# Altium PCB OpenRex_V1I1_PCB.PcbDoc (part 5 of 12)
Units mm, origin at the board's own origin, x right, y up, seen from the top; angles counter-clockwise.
Board outline 70 x 95 mm, 10 copper layers (L1, L2, L3, L4 (PWR), L5 (PWR), L6 (PWR), L7 (PWR), L8, L9, L10), stack 1.632 mm thick; 1080 components, 708 nets, 3831 pads, 2373 vias.
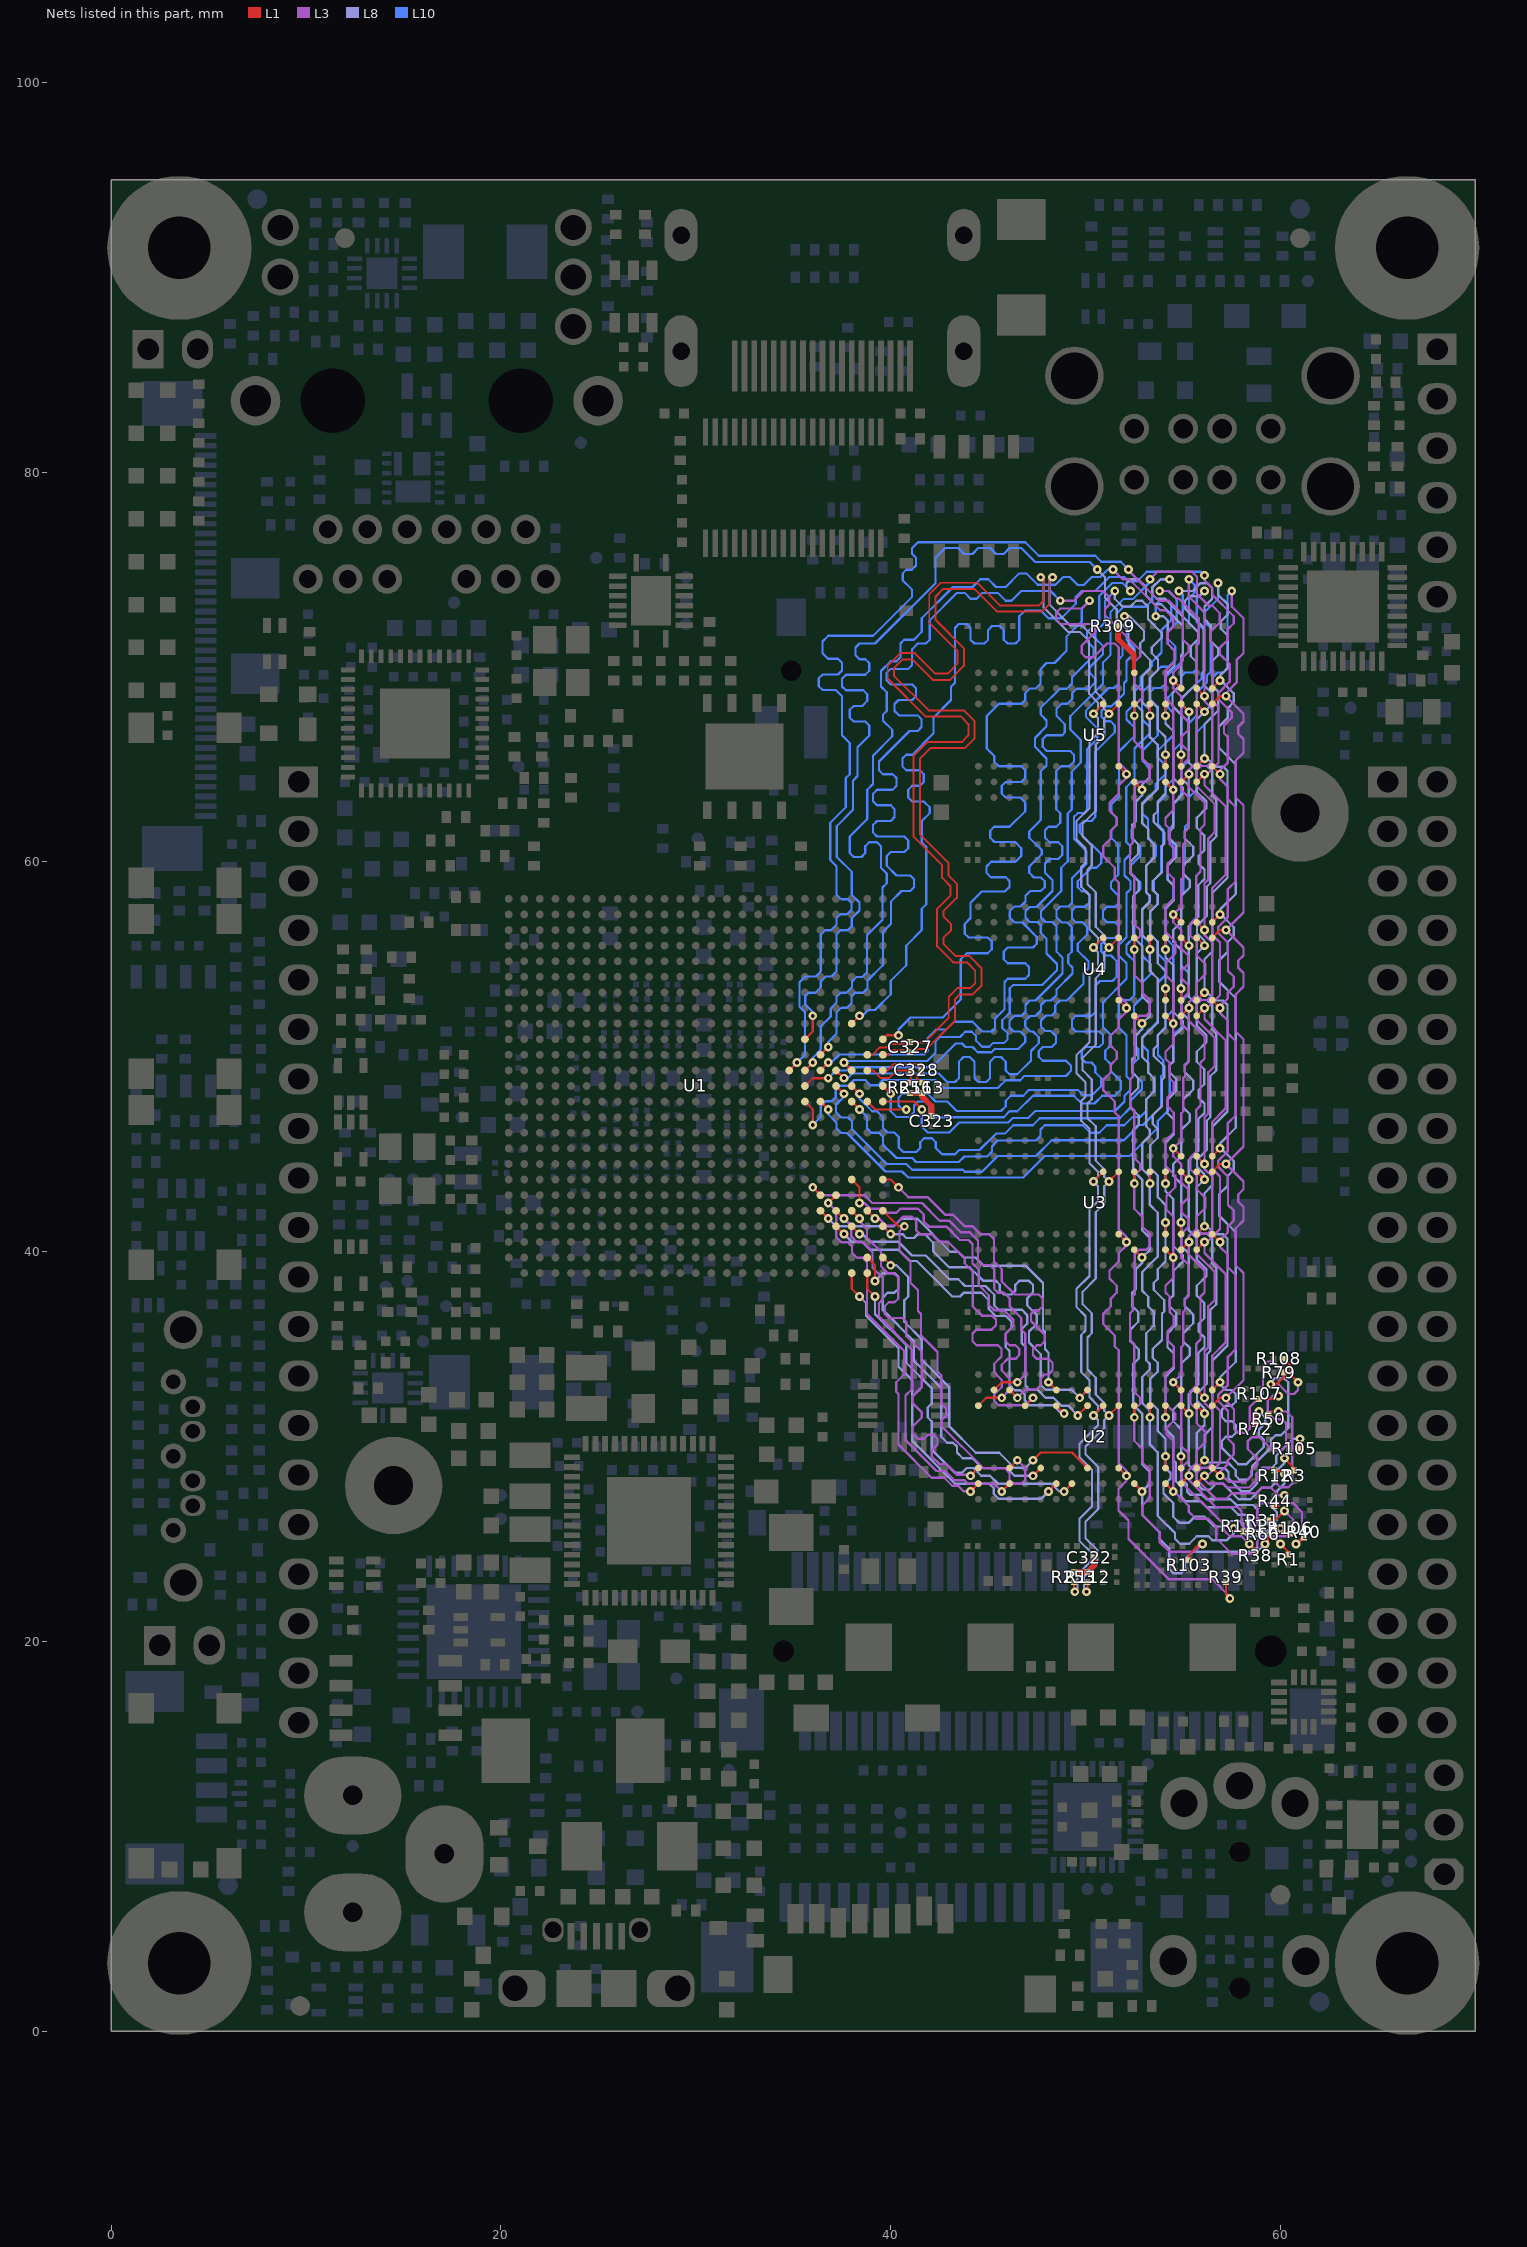
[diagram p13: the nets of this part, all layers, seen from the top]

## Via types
v1: diameter 0.45, hole 0.2, L1 to L10, tented both sides, 2369 vias
v2: diameter 1, hole 0.5, L1 to L10, tented top, 4 vias

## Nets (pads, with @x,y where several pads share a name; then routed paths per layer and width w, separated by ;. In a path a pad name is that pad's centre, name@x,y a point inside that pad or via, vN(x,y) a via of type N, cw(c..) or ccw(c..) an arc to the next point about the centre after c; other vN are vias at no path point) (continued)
DRAM3_ZQ1: R309.2 U5.L9 | length 2.7
  L1 w0.19: 52.48,70.44 52.48,69.72 U5.L9@52.5,69.7
  L1 w0.3: R309.2@51.665,72.1 51.665,71.435 52.46,70.64 52.46,70.46
DRAM_A0: R1.1 U1.AC14 U2.N3 U3.N3 U4.N3 U5.N3 | length 109.6
  L1 w0.114: v1(37.6,49.7) U1.AC14@38,49.3 ; U2.N3@54.1,28.9 v1(54.1,29.5) ; U3.N3@54.1,40.9 v1(54.1,41.5) ; U4.N3@54.1,52.9 v1(54.1,53.5) ; U5.N3@54.1,64.9 v1(54.1,65.5) ; v1(60,25) 60.4,24.6 R1.1@60.4,24.465
  L8 w0.12: v1(51.5,73.9) 51.5,73.5 51.9,73.1 52.3,73.1 52.6,73.4 52.9,73.4 53.2,73.1 53.2,72.456 53.9,71.756 53.9,71.5 53.4,71 53.4,70.7 53.715,70.385 53.715,69.859 53.3,69.444 53.3,68.3 53.7,67.9 53.7,66.8 54.1,66.4 v1(54.1,65.5) 54.1,63.5 53.7,63.1 53.7,62.6 53.5,62.4 53.5,62.044 54.035,61.509 54.035,60.935 53.92,60.82 53.92,59.476 53.45,59.006 53.45,58.55 53.7,58.3 53.7,57.844 53.315,57.459 53.315,56.29 53.7,55.905 53.7,54.8 54.1,54.4 v1(54.1,53.5) 54.1,51.5 53.7,51.1 53.7,50.6 53.5,50.4 53.5,50.044 54.035,49.509 54.035,48.935 53.92,48.82 53.92,47.476 53.45,47.006 53.45,46.55 53.7,46.3 53.7,45.844 53.315,45.459 53.315,44.29 53.7,43.905 53.7,42.8 54.1,42.4 v1(54.1,41.5) 54.1,39.5 53.7,39.1 53.7,38.6 53.5,38.4 53.5,38.044 54.035,37.509 54.035,36.935 53.92,36.82 53.92,35.476 53.45,35.006 53.45,34.55 53.7,34.3 53.7,33.844 53.315,33.459 53.315,32.29 53.7,31.905 53.7,30.8 54.1,30.4 v1(54.1,29.5) 54.1,28.9 54.355,28.645 54.355,28.355 54,28 54,27.6 54.5,27.1 54.5,26.4 54.8,26.1 55.3,26.1 55.615,26.415 56.085,26.415 56.6,25.9 57.144,25.9 57.429,26.185 57.915,26.185 58.1,26 58.1,25.6 58.315,25.385 59.615,25.385 v1(60,25)
  L10 w0.114: v1(37.6,49.7) 37.689,49.789 41.889,49.789 42.3,50.2 42.3,50.8 42.515,51.015 43.559,51.015 43.829,51.285 44.159,51.285 44.385,51.059 44.385,50.815 44.685,50.515 45.059,50.515 45.244,50.7 45.8,50.7 46,50.9 46,51.2 45.728,51.472 45.728,51.868 46.115,52.255 46.115,53.515 46.285,53.685 47.779,53.685 48.535,54.441 48.535,54.759 48,55.294 48,56.055 47.7,56.355 47.7,56.751 47.536,56.915 47.141,56.915 46.915,57.141 46.915,57.459 47.141,57.685 47.485,57.685 48.3,58.5 48.3,59.056 47.915,59.441 47.915,59.915 48.15,60.15 48.6,60.15 48.8,60.35 48.8,60.8 48.6,61 48.156,61 47.915,61.241 47.915,61.615 48.1,61.8 48.5,61.8 48.7,62 48.7,62.5 48.5,62.7 48.5,64.644 48.756,64.9 49.16,64.9 49.4,65.14 49.4,65.5 49.215,65.685 48.015,65.685 47.8,65.9 47.8,66.3 48,66.5 48.8,66.5 48.935,66.635 48.935,67.065 48.515,67.485 48.515,67.859 48.77,68.115 49.059,68.115 49.315,68.371 49.315,68.659 49.541,68.885 50.185,68.885 50.5,69.2 50.5,69.4 50.2,69.7 50.2,69.969 50.9,70.669 50.9,71.056 50.5,71.456 50.5,71.8 51,72.3 51,73.4 v1(51.5,73.9)
DRAM_A1: R3.1 U1.AB14 U2.P7 U3.P7 U4.P7 U5.P7 | length 109.5
  L1 w0.114: U1.AB14@37.2,49.3 v1(37.6,48.9) ; U2.P7@54.9,32.1 v1(55.3,31.7) ; U3.P7@54.9,44.1 v1(55.3,43.7) ; U4.P7@54.9,56.1 v1(55.3,55.7) ; U5.P7@54.9,68.1 v1(55.3,67.7) ; v1(60.2,29.4) 60.7,28.9 R3.1@60.7,28.765
  L8 w0.12: v1(54.3,74.5) 53.844,74.5 53.415,74.071 53.415,73.741 53.656,73.5 54.08,73.5 55.785,71.795 55.785,71.441 55.4,71.056 55.4,70.544 55.7,70.244 55.7,69.156 54.944,68.4 54.944,68.056 v1(55.3,67.7) 55.3,65.082 55.7,64.682 55.7,63.6 56.2,63.1 56.2,62.756 55.7,62.256 55.7,61.744 56.085,61.359 56.085,60.585 55.81,60.31 55.81,59.89 56.1,59.6 56.1,59.115 55.785,58.8 55.785,57.181 55.3,56.696 v1(55.3,55.7) 55.3,53.082 55.7,52.682 55.7,51.6 56.2,51.1 56.2,50.756 55.7,50.256 55.7,49.744 56.085,49.359 56.085,48.585 55.81,48.31 55.81,47.89 56.1,47.6 56.1,47.115 55.785,46.8 55.785,45.181 55.3,44.696 v1(55.3,43.7) 55.3,41.082 55.7,40.682 55.7,39.6 56.2,39.1 56.2,38.756 55.7,38.256 55.7,37.744 56.085,37.359 56.085,36.585 55.81,36.31 55.81,35.89 56.1,35.6 56.1,35.115 55.785,34.8 55.785,33.181 55.3,32.696 v1(55.3,31.7) 55.3,29.044 55.7,28.644 55.7,28.1 56,27.8 56.4,27.8 56.7,28.1 57.044,28.1 57.844,27.3 58.456,27.3 59.056,27.9 59.5,27.9 59.815,28.215 59.815,28.775 60.2,29.16 v1(60.2,29.4)
  L10 w0.114: v1(37.6,48.9) 37.796,48.9 38.033,49.137 42.463,49.137 42.9,48.7 43.3,48.7 43.5,48.9 43.5,49.744 43.741,49.985 44.059,49.985 44.3,49.744 44.3,48.9 44.5,48.7 44.9,48.7 45.1,48.9 45.1,49.744 45.341,49.985 45.659,49.985 45.9,49.744 45.9,49.3 46.1,49.1 46.5,49.1 47.2,49.8 47.2,50.3 47.6,50.7 47.6,51 47.3,51.3 47.156,51.3 46.9,51.556 46.9,51.844 47.146,52.091 47.435,52.091 47.715,52.371 47.715,52.659 47.941,52.885 48.229,52.885 48.515,53.171 48.515,53.459 49.33,54.274 49.33,54.585 49.115,54.8 49.115,55.215 49.285,55.385 49.285,56.659 49.059,56.885 48.771,56.885 48.515,57.141 48.515,57.515 48.715,57.715 49.115,57.715 49.3,57.9 49.3,59.156 50.05,59.906 50.05,60.55 49.4,61.2 49.4,62.3 49.6,62.5 49.9,62.5 50.085,62.685 50.085,65.785 50.6,66.3 50.6,66.856 50.015,67.441 50.015,67.759 51.171,68.915 51.459,68.915 51.685,69.141 51.685,70.385 51.9,70.6 51.9,71.2 51.615,71.485 51.615,72.759 51.941,73.085 53.085,73.085 53.415,73.415 53.415,74.059 53.856,74.5 v1(54.3,74.5)
DRAM_A2: R12.1 U1.AA14 U2.P3 U3.P3 U4.P3 U5.P3 | length 109.6
  L1 w0.114: U1.AA14@36.4,49.3 v1(36.8,49.7) ; U2.P3@54.9,28.9 v1(54.9,29.5) ; U3.P3@54.9,40.9 v1(54.9,41.5) ; U4.P3@54.9,52.9 v1(54.9,53.5) ; U5.P3@54.9,64.9 v1(54.9,65.5) ; R12.1@59.7,28.765 60.035,28.765 v1(60.2,28.6)
  L8 w0.12: v1(52.3,73.9) 52.1,74.1 52.1,74.3 52.3,74.5 52.7,74.5 53.1,74.1 53.1,73.66 53.54,73.22 53.88,73.22 55,72.1 55,70.7 54.9,70.6 54.9,69.1 54.456,68.656 54.456,68 54.9,67.556 v1(54.9,65.5) 54.9,64.3 55.3,63.9 55.3,61.8 55.085,61.585 55.085,61.215 55.525,60.775 55.525,60.325 55,59.8 55,59.4 55.35,59.05 55.35,58.694 54.9,58.244 54.9,56.9 54.5,56.5 54.5,55.9 54.9,55.5 v1(54.9,53.5) 54.9,52.3 55.3,51.9 55.3,49.8 55.085,49.585 55.085,49.215 55.525,48.775 55.525,48.325 55,47.8 55,47.4 55.35,47.05 55.35,46.694 54.9,46.244 54.9,44.9 54.5,44.5 54.5,43.9 54.9,43.5 v1(54.9,41.5) 54.9,40.3 55.3,39.9 55.3,37.8 55.085,37.585 55.085,37.215 55.525,36.775 55.525,36.325 55,35.8 55,35.4 55.35,35.05 55.35,34.694 54.9,34.244 54.9,32.3 54.5,31.9 54.5,31.3 54.9,30.9 v1(54.9,29.5) 54.915,29.485 54.915,28.341 55.2,28.055 55.2,27.7 55.38,27.52 55.98,27.52 56.2,27.3 57.436,27.3 57.736,27 58.6,27 58.8,26.8 58.8,26.2 59,26 59.6,26 59.815,26.215 59.815,26.629 59.5,26.944 59.5,27.256 59.8,27.556 59.8,27.7 60.2,28.1 v1(60.2,28.6)
  L10 w0.114: v1(36.8,49.7) 36.955,49.7 37.37,50.115 41.715,50.115 41.9,50.3 41.9,50.967 42.325,51.392 42.847,51.392 43.256,51.8 44.2,51.8 44.7,51.3 45.2,51.3 45.348,51.448 45.348,51.948 45.835,52.435 45.835,53.835 46,54 46.9,54 47.1,54.2 47.1,54.6 46.9,54.8 46,54.8 45.8,55 45.8,55.4 46,55.6 47.3,55.6 47.5,55.8 47.5,56.144 46.759,56.885 46.37,56.885 46.115,57.141 46.115,57.459 46.371,57.715 46.659,57.715 46.915,57.971 46.915,58.259 47.156,58.5 47.7,58.5 47.9,58.7 47.9,59 47.7,59.2 47.356,59.2 47.115,59.441 47.115,59.759 47.75,60.394 47.75,60.606 47.115,61.241 47.115,61.559 47.7,62.144 47.7,64.644 48,64.944 48,65.3 47.4,65.9 47.4,66.356 48,66.956 48,67.256 47.7,67.556 47.7,67.9 48.685,68.885 49.029,68.885 49.3,69.156 49.3,69.465 50.4,70.565 50.4,71 50.075,71.325 50.075,71.785 50.7,72.41 50.7,73.644 51.356,74.3 51.9,74.3 v1(52.3,73.9)
DRAM_A3: R31.1 U1.Y14 U2.N2 U3.N2 U4.N2 U5.N2 | length 109.5
  L1 w0.114: U1.Y14@35.6,49.3 v1(36,49.7) ; U2.N2@54.1,28.1 v1(54.5,27.7) ; U3.N2@54.1,40.1 v1(54.5,39.7) ; U4.N2@54.1,52.1 v1(54.5,51.7) ; U5.N2@54.1,64.1 v1(54.5,63.7) ; R31.1@59.365,26.2 59.7,26.2 v1(60.2,26.7)
  L3 w0.12: v1(51.4,75) 51.9,74.5 52.244,74.5 53.834,72.91 54.09,72.91 54.5,72.5 54.5,72.044 54.215,71.759 54.215,71.185 54.58,70.82 54.58,70.28 54.115,69.815 54.115,68.385 54.5,68 v1(54.5,63.7) 54.5,62.656 54.1,62.256 54.1,61.9 54.315,61.685 54.315,60.9 54.525,60.69 54.525,60.238 54.215,59.928 54.215,59.441 54.525,59.131 54.525,58.125 54.1,57.7 54.1,56.4 54.6,55.9 54.6,55.3 54.15,54.85 54.15,54.15 54.5,53.8 v1(54.5,51.7) 54.5,50.656 54.1,50.256 54.1,49.9 54.315,49.685 54.315,48.9 54.525,48.69 54.525,48.238 54.215,47.928 54.215,47.441 54.525,47.131 54.525,46.125 54.1,45.7 54.1,44.4 54.6,43.9 54.6,43.3 54.15,42.85 54.15,42.15 54.5,41.8 v1(54.5,39.7) 54.5,38.656 54.1,38.256 54.1,37.9 54.315,37.685 54.315,36.9 54.525,36.69 54.525,36.238 54.215,35.928 54.215,35.441 54.525,35.131 54.525,34.125 54.1,33.7 54.1,32.2 54.6,31.7 54.6,31.4 54.15,30.95 54.15,30.65 54.5,30.3 v1(54.5,27.7) 54.544,27.7 55.285,26.959 55.285,26.671 55.656,26.3 56.3,26.3 56.7,25.9 56.7,25.3 57.5,24.5 58.556,24.5 58.8,24.744 58.8,25.144 59.056,25.4 60.45,25.4 60.65,25.6 60.65,26.25 v1(60.2,26.7)
  L10 w0.114: v1(36,49.7) 36,49.956 36.415,50.371 36.415,51.56 36.925,52.07 36.925,52.481 37.215,52.771 37.215,53.059 37.441,53.285 37.729,53.285 38.015,53.571 38.015,53.859 38.241,54.085 38.529,54.085 38.785,54.341 38.785,56.229 39.585,57.029 39.585,58.685 39.8,58.9 39.8,59.404 39.5,59.704 39.5,60.8 39.3,61 38.9,61 38.7,60.8 38.7,60.45 38.5,60.25 38.1,60.25 37.9,60.45 37.9,61.3 38.8,62.2 38.8,63.7 39.09,63.99 39.09,65.446 40.085,66.441 40.085,66.771 39.6,67.256 39.6,67.544 39.8,67.744 39.8,68.7 39.5,69 39.5,69.796 40,70.296 40.296,70.296 40.5,70.5 40.5,71.2 40.7,71.4 41.2,71.4 41.6,71.8 41.6,72.5 43.2,74.1 44.2,74.1 44.6,74.5 45.004,74.5 45.404,74.1 45.9,74.1 46.6,74.8 46.956,74.8 47.541,74.215 48.459,74.215 48.859,74.615 49.185,74.615 49.6,74.2 49.9,74.2 50.315,74.615 50.759,74.615 51.144,75 v1(51.4,75)
DRAM_A4: R38.1 U1.W14 U2.P8 U3.P8 U4.P8 U5.P8 | length 109.4
  L1 w0.114: U1.W14@34.8,49.3 v1(35.2,49.7) ; v1(54.5,33.3) U2.P8@54.9,32.9 ; v1(54.5,45.3) U3.P8@54.9,44.9 ; v1(54.5,57.3) U4.P8@54.9,56.9 ; v1@54.5,69.3 U5.P8@54.9,68.9 ; v1(58.4,25) 58.7,24.7 R38.1@58.7,24.665
  L3 w0.12: v1(52.2,75) 52.2,74.955 53.755,73.4 54.28,73.4 55,72.68 55,71.4 55.3,71.1 55.3,70.8 54.9,70.4 54.9,70.1 54.5,69.7 v1(54.5,69.3) 54.5,68.9 54.9,68.5 54.9,67.556 55.275,67.181 55.275,66.775 54.9,66.4 54.9,66.044 55.3,65.644 55.3,65.3 54.9,64.9 54.9,63.7 55.3,63.3 55.3,61.744 55.1,61.544 55.1,61 55.015,60.915 55.015,59.2 54.915,59.1 54.915,57.715 v1(54.5,57.3) 54.5,56.9 54.9,56.5 54.9,55.556 55.275,55.181 55.275,54.775 54.9,54.4 54.9,54.044 55.3,53.644 55.3,53.3 54.9,52.9 54.9,51.7 55.3,51.3 55.3,49.744 55.1,49.544 55.1,49 55.015,48.915 55.015,47.2 54.915,47.1 54.915,45.715 v1(54.5,45.3) 54.5,44.9 54.9,44.5 54.9,43.556 55.275,43.181 55.275,42.775 54.9,42.4 54.9,42.044 55.3,41.644 55.3,41.3 54.9,40.9 54.9,39.7 55.3,39.3 55.3,37.744 55.1,37.544 55.1,37 55.015,36.915 55.015,35.2 54.915,35.1 54.915,33.715 v1(54.5,33.3) 54.9,32.9 54.9,30.044 55.3,29.644 55.3,29.3 54.9,28.9 54.9,28.2 57.1,26 57.1,25.7 57.4,25.4 58,25.4 v1(58.4,25)
  L10 w0.114: v1(35.2,49.7) 35.6,50.1 35.6,52.29 35.325,52.565 35.325,53.825 35.615,54.115 36.159,54.115 36.415,54.371 36.415,56.259 36.641,56.485 36.929,56.485 37.215,56.771 37.215,57.1 37.43,57.315 37.759,57.315 37.985,57.541 37.985,57.9 37.8,58.085 37.471,58.085 37.215,58.341 37.215,59.785 36.9,60.1 36.9,62 37.7,62.8 37.7,64.3 37.9,64.5 37.9,66.1 37.5,66.5 37.5,68.5 37.185,68.815 36.515,68.815 36.315,69.015 36.315,69.415 36.515,69.615 37.3,69.615 37.5,69.815 37.5,70.215 37.3,70.415 36.785,70.415 36.5,70.7 36.5,71.3 36.8,71.6 39.1,71.6 41.1,73.6 41.1,73.956 40.615,74.441 40.615,74.8 40.8,74.985 41.085,74.985 41.3,75.2 41.3,75.6 41.1,75.8 41.1,76.1 41.4,76.4 46.9,76.4 47.6,75.7 50.5,75.7 50.8,75.4 51.8,75.4 v1(52.2,75)
DRAM_A5: R40.1 U1.AE13 U2.P2 U3.P2 U4.P2 U5.P2 | length 109.4
  L1 w0.114: U1.AE13@39.6,48.5 v1(40,48.1) ; U2.P2@54.9,28.1 v1(55.3,28.5) ; U3.P2@54.9,40.1 v1(55.3,40.5) ; U4.P2@54.9,52.1 v1(55.3,52.5) ; U5.P2@54.9,64.1 v1(55.3,64.5) ; v1(60.8,25) 60.865,25 R40.1@61.2,25.335
  L3 w0.12: v1(53.8,73.9) 54.256,73.9 54.641,73.515 54.785,73.515 55.8,72.5 55.8,71.2 55.7,71.1 55.7,65.118 55.3,64.718 v1(55.3,64.5) 55.3,63.829 56.1,63.029 56.1,61.9 55.9,61.7 55.9,59.5 55.685,59.285 55.685,57.141 55.375,56.831 55.375,56.225 55.7,55.9 55.7,55.2 56.15,54.75 56.15,54.25 55.7,53.8 55.7,53.2 55.3,52.8 v1(55.3,52.5) 55.3,51.829 56.1,51.029 56.1,49.9 55.9,49.7 55.9,47.5 55.685,47.285 55.685,45.141 55.375,44.831 55.375,44.225 55.7,43.9 55.7,43.2 56.15,42.75 56.15,42.25 55.7,41.8 55.7,41.2 55.3,40.8 v1(55.3,40.5) 55.3,39.829 56.1,39.029 56.1,37.9 55.9,37.7 55.9,35.5 55.685,35.285 55.685,33.141 55.375,32.831 55.375,32.225 55.7,31.9 55.7,31.2 56.15,30.75 56.15,30.25 55.7,29.8 55.7,29.2 55.3,28.8 v1(55.3,28.5) 55.3,28.282 56.682,26.9 57.8,26.9 58,26.7 58,26 58.2,25.8 58.6,25.8 58.8,26 58.8,26.9 59,27.1 60.635,27.1 61.1,26.635 61.1,25.3 v1(60.8,25)
  L10 w0.114: v1(40,48.1) 40,47.2 40.285,46.915 40.959,46.915 41.2,47.156 41.2,47.5 41.4,47.7 41.8,47.7 42,47.5 42,47.1 42.2,46.9 45.8,46.9 46.1,47.2 46.5,47.2 47.3,48 49.4,48 49.8,47.6 50.456,47.6 50.856,48 51.5,48 51.8,48.3 51.8,48.756 51.3,49.256 51.3,49.6 51.006,49.894 51.006,50.306 51.3,50.6 51.3,51.1 50.9,51.5 50.9,52.8 52.1,54 52.1,54.8 51.7,55.2 51.7,55.735 52.1,56.135 52.1,58.4 52.3,58.6 52.3,59 52,59.3 52,60.1 52.3,60.4 52.3,60.8 52.085,61.015 52.085,63.825 52.515,64.255 52.515,65.815 53.3,66.6 53.3,66.9 52.9,67.3 52.9,68.7 53.315,69.115 53.315,69.459 53.871,70.015 54.259,70.015 54.6,70.356 54.6,71.056 54.215,71.441 54.215,71.815 54.68,72.28 54.68,73.476 54.256,73.9 v1(53.8,73.9)
DRAM_A6: R44.1 U1.AC13 U2.R8 U3.R8 U4.R8 U5.R8 | length 109.4
  L1 w0.114: U1.AC13@38,48.5 v1(38.4,48.1) ; U2.R8@55.7,32.9 v1(56.1,32.5) ; U3.R8@55.7,44.9 v1(56.1,44.5) ; U4.R8@55.7,56.9 v1(56.1,56.5) ; U5.R8@55.7,68.9 v1(56.1,68.5) ; R44.1@59.7,26.935 59.869,26.935 60.2,27.266 v1(60.2,27.5)
  L3 w0.12: v1(55.3,74.5) 55.3,73.6 56.1,72.8 v1(56.1,68.5) 56.1,68.244 56.5,67.844 56.5,65.156 56.259,64.915 55.915,64.915 55.7,64.7 55.7,63.882 56.625,62.957 56.625,61.525 56.3,61.2 56.3,59.1 56.1,58.9 v1(56.1,56.5) 56.1,56.244 56.5,55.844 56.5,53.156 56.259,52.915 55.915,52.915 55.7,52.7 55.7,51.882 56.625,50.957 56.625,49.525 56.3,49.2 56.3,47.1 56.1,46.9 v1(56.1,44.5) 56.1,44.244 56.5,43.844 56.5,41.156 56.259,40.915 55.915,40.915 55.7,40.7 55.7,39.882 56.625,38.957 56.625,37.525 56.3,37.2 56.3,35.1 56.1,34.9 v1(56.1,32.5) 56.1,32.244 56.5,31.844 56.5,29.156 56.259,28.915 55.971,28.915 55.7,28.644 55.7,28.304 56.689,27.315 57.215,27.315 57.5,27.6 58.756,27.6 59.041,27.885 59.515,27.885 59.9,27.5 v1(60.2,27.5)
  L10 w0.114: v1(38.4,48.1) 38.4,47.85 39.05,47.2 39.3,47.2 39.6,46.9 39.6,46.356 39.841,46.115 40.185,46.115 40.415,45.885 40.415,45.341 40.641,45.115 41.315,45.115 41.515,45.315 41.515,45.615 41.715,45.815 42.115,45.815 42.315,45.615 42.315,45.315 42.63,45 43.3,45 43.515,45.215 44.559,45.215 45.4,46.056 45.856,46.056 46.285,46.485 47.285,46.485 47.65,46.85 51.75,46.85 52.3,47.4 52.3,47.744 52.9,48.344 52.9,48.7 52.415,49.185 52.415,49.615 52.7,49.9 52.7,50.4 52.485,50.615 52.485,52.629 52.9,53.044 52.9,53.8 53.35,54.25 53.35,54.75 52.9,55.2 52.9,57.556 53.285,57.941 53.285,58.259 53.1,58.444 53.1,59.8 53.6,60.3 53.6,60.856 53.2,61.256 53.2,62.2 52.9,62.5 52.9,63 53.6,63.7 53.6,64 54.1,64.5 54.1,64.956 53.7,65.356 53.7,65.7 54.485,66.485 54.485,67.659 54.244,67.9 54.244,68.444 54.9,69.1 54.9,69.5 55.115,69.715 55.515,69.715 55.685,69.885 55.685,71.285 55.8,71.4 55.8,71.744 55.3,72.244 55.3,73.52 55.6,73.82 55.6,74.2 v1(55.3,74.5)
DRAM_A7: R50.1 U1.Y13 U2.R2 U3.R2 U4.R2 U5.R2 | length 109.5
  L1 w0.114: U1.Y13@35.6,48.5 36,48.9 v1(36.8,48.9) ; U2.R2@55.7,28.1 v1(56.1,28.5) ; U3.R2@55.7,40.1 v1(56.1,40.5) ; U4.R2@55.7,52.1 v1(56.1,52.5) ; U5.R2@55.7,64.1 v1(56.1,64.5) ; R50.1@59.4,31.665 59.535,31.8 v1(59.9,31.8)
  L3 w0.12: v1(53.3,74.5) 53.685,74.885 55.459,74.885 55.715,74.629 55.715,73.741 56.1,73.356 56.318,73.137 56.507,73.137 56.885,72.759 56.885,72.285 56.415,71.815 56.415,71.3 56.5,71.215 56.5,68.26 56.82,67.94 56.82,65.08 56.24,64.5 v1(56.1,64.5) 56.1,63.934 57.185,62.849 57.185,59.341 56.5,58.656 56.5,56.26 56.9,55.86 56.9,53.16 56.24,52.5 v1(56.1,52.5) 56.1,51.934 57.185,50.849 57.185,47.341 56.5,46.656 56.5,44.26 56.9,43.86 56.9,41.16 56.24,40.5 v1(56.1,40.5) 56.1,39.934 57.185,38.849 57.185,35.341 56.5,34.656 56.5,32.24 56.9,31.84 56.9,29.16 56.24,28.5 v1(56.1,28.5) 56.1,28.3 56.315,28.085 57.059,28.085 57.244,27.9 58.4,27.9 58.765,28.265 58.765,28.61 59.041,28.885 59.515,28.885 59.74,28.66 59.74,28.16 59.985,27.915 60.415,27.915 60.6,28.1 60.6,31.5 60.3,31.8 v1(59.9,31.8)
  L10 w0.114: v1(36.8,48.9) 37.2,49.3 37.744,49.3 37.907,49.463 42.119,49.463 43.341,50.685 43.659,50.685 43.844,50.5 44.2,50.5 44.465,50.235 45.175,50.235 45.34,50.4 46.544,50.4 46.9,50.756 46.9,51.044 46.644,51.3 46.3,51.3 46.1,51.5 46.1,51.844 46.356,52.1 46.715,52.1 46.915,52.3 46.915,52.659 47.141,52.885 47.429,52.885 48.815,54.271 48.815,55.085 48.515,55.385 48.515,56.685 48.285,56.915 47.941,56.915 47.715,57.141 47.715,57.459 48.756,58.5 48.756,59.7 49.08,60.024 49.08,62.484 49.285,62.689 49.285,64.629 49.75,65.094 49.75,66.25 49.215,66.785 49.215,67.471 50.9,69.156 50.9,70.244 51.285,70.629 51.285,72.825 51.94,73.48 52.424,73.48 53.3,74.356 v1(53.3,74.5)
DRAM_A8: R72.1 U1.AB13 U2.T8 U3.T8 U4.T8 U5.T8 | length 109.5
  L1 w0.114: U1.AB13@37.2,48.5 v1(37.6,48.1) ; U2.T8@56.5,32.9 v1(56.9,33.3) ; U3.T8@56.5,44.9 v1(56.9,45.3) ; U4.T8@56.5,56.9 v1(56.9,57.3) ; U5.T8@56.5,68.9 v1@56.9,69.3 ; R72.1@58.7,31.165 58.7,31.6 v1(58.9,31.8)
  L8 w0.12: v1(56.8,74.3) 56.8,73.7 57.3,73.2 57.3,72.7 56.932,72.332 56.932,71.968 57.3,71.6 57.3,69.956 56.9,69.556 v1(56.9,69.3) 56.944,69.3 57.6,68.644 57.6,68.2 57.3,67.9 57.3,67.4 56.845,66.945 56.845,65.855 57.7,65 57.7,58.356 56.9,57.556 v1(56.9,57.3) 56.944,57.3 57.6,56.644 57.6,56.2 57.3,55.9 57.3,55.4 56.845,54.945 56.845,53.855 57.7,53 57.7,46.356 56.9,45.556 v1(56.9,45.3) 56.944,45.3 57.6,44.644 57.6,44.2 57.3,43.9 57.3,43.4 56.845,42.945 56.845,41.855 57.7,41 57.7,34.356 56.9,33.556 v1(56.9,33.3) 56.9,33.2 57.2,32.9 57.5,32.9 57.7,32.7 57.7,32.3 57.5,32.1 57.2,32.1 57,31.9 57,31.5 57.2,31.3 57.5,31.3 57.7,31.1 57.7,30.7 57.5,30.5 57.2,30.5 57,30.3 57,29.934 57.834,29.1 58.26,29.1 59.15,29.99 59.15,30.35 58.9,30.6 58.9,30.88 59.22,31.2 59.22,31.48 v1(58.9,31.8)
  L10 w0.114: v1(37.6,48.1) 37.6,47.945 37.2,47.545 37.2,47.156 37.471,46.885 37.815,46.885 38.015,46.685 38.015,46.285 39.8,44.5 40.8,44.5 41.1,44.2 43.7,44.2 43.8,44.1 44.69,44.1 45.5,44.91 47.454,44.91 48.259,45.715 51.971,45.715 52.756,46.5 52.944,46.5 53.885,47.441 53.885,49 53.985,49.1 53.985,49.815 53.715,50.085 53.715,51.115 54.1,51.5 54.1,52 54.5,52.4 54.5,55.7 54.1,56.1 54.1,57.7 54.5,58.1 54.5,58.8 54.215,59.085 54.215,59.815 54.5,60.1 54.5,60.9 54.265,61.135 54.265,61.665 54.515,61.915 54.515,62.959 54.9,63.344 54.9,64.8 55.3,65.2 55.3,67.1 55.715,67.515 55.715,68.695 56.235,69.215 56.235,69.575 56.415,69.755 56.415,71.995 56.1,72.31 56.1,72.8 56.8,73.5 v1(56.8,74.3)
DRAM_A9: R79.1 U1.AE12 U2.R3 U3.R3 U4.R3 U5.R3 | length 109.4
  L1 w0.114: U1.AE12@39.6,47.7 41.2,47.7 v1(41.6,47.3) ; U2.R3@55.7,28.9 v1(56.1,29.3) ; U3.R3@55.7,40.9 v1(56.1,41.3) ; U4.R3@55.7,52.9 v1(56.1,53.3) ; U5.R3@55.7,64.9 v1(56.1,65.3) ; v1(59.5,33.2) 59.8,33.2 60.165,33.565 R79.1@60.165,33.8
  L8 w0.12: v1(54.8,73.9) 55.5,73.9 55.9,74.3 56.244,74.3 56.485,74.059 56.485,73.485 56.1,73.1 56.1,72.456 56.415,72.141 56.415,71.341 56.8,70.956 56.8,70.6 56.515,70.315 56.515,69.025 56.8,68.74 56.8,67.756 56.1,67.056 v1(56.1,65.3) 56.24,65.3 56.655,64.885 57.059,64.885 57.285,64.659 57.285,59.185 56.515,58.415 56.515,55.415 56.1,55 v1(56.1,53.3) 56.24,53.3 56.655,52.885 57.059,52.885 57.285,52.659 57.285,47.185 56.515,46.415 56.515,43.415 56.1,43 v1(56.1,41.3) 56.24,41.3 56.655,40.885 57.059,40.885 57.285,40.659 57.285,35.185 56.515,34.415 56.515,31.015 56.1,30.6 v1(56.1,29.3) 56.22,29.18 57.302,29.18 57.7,28.782 57.7,28.5 57.9,28.3 58.3,28.3 58.535,28.535 58.535,28.979 59.515,29.959 59.515,30.359 59.741,30.585 60.029,30.585 60.4,30.956 60.4,33.3 60.2,33.5 59.7,33.5 59.5,33.3 v1(59.5,33.2)
  L10 w0.114: v1(41.6,47.3) 41.6,46.415 41.9,46.115 43,46.115 43.505,46.62 46.02,46.62 46.258,46.858 47.058,46.858 47.415,47.215 51.515,47.215 52,47.7 52,48 52.3,48.3 52.3,48.8 52.1,49 52.1,51.1 51.7,51.5 51.7,52.7 51.915,52.915 52.259,52.915 52.5,53.156 52.5,54.9 52.1,55.3 52.1,55.738 52.5,56.138 52.5,58.3 52.8,58.6 52.8,58.956 52.315,59.441 52.315,59.815 52.8,60.3 52.8,60.8 52.365,61.235 52.365,61.665 52.515,61.815 52.515,63.859 52.771,64.115 53.115,64.115 53.285,64.285 53.285,64.815 52.915,65.185 52.915,65.715 53.7,66.5 53.7,67.956 53.315,68.341 53.315,68.705 53.525,68.915 53.859,68.915 54.085,69.141 54.085,69.445 54.985,70.345 54.985,73.715 v1(54.8,73.9)
DRAM_A10: R103.1 U1.AA15 U2.L7 U3.L7 U4.L7 U5.L7 | length 109.5
  L1 w0.114: U1.AA15@36.4,50.1 v1(36.8,50.5) ; v1(52.5,31.5) U2.L7@52.5,32.1 ; v1(52.5,43.5) U3.L7@52.5,44.1 ; v1(52.5,55.5) U4.L7@52.5,56.1 ; v1(52.5,67.5) U5.L7@52.5,68.1 ; R103.1@55.3,24.165 55.3,24.45 55.85,25 v1(56,25)
  L3 w0.12: v1(48.7,73.4) 49.4,73.4 49.9,73.9 50.9,73.9 51.22,73.58 51.22,73.2 51,72.98 51,72.656 52.8,70.856 52.8,70.544 52.5,70.244 52.5,69.164 52.9,68.764 52.9,68.4 52.5,68 v1(52.5,67.5) 52.5,66.2 52.9,65.8 52.9,65.3 53.3,64.9 53.3,64.3 53.098,64.098 52.754,64.098 52.515,63.859 52.515,61.815 52.415,61.715 52.415,60.964 52.275,60.824 52.275,59.481 52.5,59.256 52.5,56.8 52.8,56.5 52.8,56.2 52.5,55.9 v1(52.5,55.5) 52.5,54.2 52.9,53.8 52.9,53.3 53.3,52.9 53.3,52.3 53.098,52.098 52.754,52.098 52.515,51.859 52.515,49.815 52.415,49.715 52.415,48.964 52.275,48.824 52.275,47.481 52.5,47.256 52.5,44.8 52.8,44.5 52.8,44.2 52.5,43.9 v1(52.5,43.5) 52.5,42.2 52.9,41.8 52.9,41.3 53.3,40.9 53.3,40.3 53.098,40.098 52.754,40.098 52.515,39.859 52.515,37.815 52.415,37.715 52.415,36.964 52.275,36.824 52.275,35.481 52.5,35.256 52.5,32.8 52.8,32.5 52.8,32.2 52.5,31.9 v1(52.5,31.5) 52.5,30.3 52.9,29.9 52.9,29.2 53.3,28.8 53.3,27.366 52.9,26.966 52.9,26.5 53.8,25.6 53.8,25.1 54.3,24.6 55.6,24.6 v1(56,25)
  L10 w0.114: v1(36.8,50.5) 36.8,50.756 37.215,51.171 37.215,52.259 37.471,52.515 37.759,52.515 37.985,52.741 37.985,53.1 38.17,53.285 38.585,53.285 38.815,53.515 38.815,53.915 39.6,54.7 39.6,56.4 40.01,56.81 40.01,57.956 40.554,58.5 41,58.5 41.2,58.7 41.2,59.1 41,59.3 40.3,59.3 39.8,59.8 39.8,60.3 40,60.5 40.7,60.5 40.9,60.7 40.9,61.1 40.7,61.3 39.3,61.3 39.1,61.5 39.1,61.9 39.3,62.1 40,62.1 40.2,62.3 40.2,62.7 40,62.9 39.3,62.9 39.1,63.1 39.1,63.5 39.3,63.7 40.1,63.7 40.3,63.9 40.3,64.3 40.1,64.5 39.6,64.5 39.4,64.7 39.4,65.15 40.965,66.715 41.385,66.715 41.585,66.915 41.585,67.315 41.385,67.515 40.8,67.515 40.429,67.515 40.2,67.744 40.2,68.1 40.4,68.3 41.1,68.3 41.3,68.5 41.3,68.9 41.1,69.1 40,69.1 39.8,69.3 39.8,69.7 40,69.9 40.9,69.9 41.1,70.1 41.1,70.904 41.396,71.2 41.8,71.2 42,71.4 42,72.4 43.4,73.8 43.8,73.8 44.1,73.5 44.4,73.5 44.7,73.8 45.5,73.8 45.9,73.4 46.2,73.4 46.7,73.9 48.2,73.9 v1(48.7,73.4)
DRAM_A11: R105.1 U1.AC12 U2.R7 U3.R7 U4.R7 U5.R7 | length 109.5
  L1 w0.114: U1.AC12@38,47.7 v1(38.4,47.3) ; U2.R7@55.7,32.1 v1(56.1,31.7) ; U3.R7@55.7,44.1 v1(56.1,43.7) ; U4.R7@55.7,56.1 v1(56.1,55.7) ; U5.R7@55.7,68.1 v1(56.1,67.7) ; R105.1@60.965,29.9 60.965,30.365 v1(61,30.4)
  L8 w0.12: v1(56.1,73.9) 55.82,73.62 55.32,73.62 55.1,73.4 55.1,73 56.065,72.035 56.065,69.079 56.485,68.659 56.485,68.085 v1(56.1,67.7) 55.7,67.3 55.7,65.156 55.941,64.915 56.229,64.915 56.5,64.644 56.5,63.4 56.7,63.2 56.7,61.3 56.4,61 56.4,58.9 56.22,58.72 56.22,57.22 55.715,56.715 55.715,56.341 56.1,55.956 v1(56.1,55.7) 55.7,55.3 55.7,53.156 55.941,52.915 56.229,52.915 56.5,52.644 56.5,51.4 56.7,51.2 56.7,49.3 56.4,49 56.4,46.9 56.22,46.72 56.22,45.22 55.715,44.715 55.715,44.341 56.1,43.956 v1(56.1,43.7) 55.7,43.3 55.7,41.156 55.941,40.915 56.229,40.915 56.5,40.644 56.5,39.4 56.7,39.2 56.7,37.3 56.4,37 56.4,34.9 56.22,34.72 56.22,33.22 55.715,32.715 55.715,32.341 56.1,31.956 v1(56.1,31.7) 56.1,31.1 55.7,30.7 55.7,29.1 55.9,28.9 57.129,28.9 57.329,28.7 57.329,28.371 58,27.7 58.4,27.7 58.815,28.115 58.815,28.66 59.07,28.915 59.559,28.915 59.785,29.141 59.785,29.541 60.644,30.4 v1(61,30.4)
  L10 w0.114: v1(38.4,47.3) 38.785,46.915 38.785,46.315 39,46.1 39.4,46.1 39.6,45.9 39.6,45.5 40.3,44.8 41.1,44.8 41.3,44.6 43.5,44.6 43.785,44.885 44.95,44.885 45.2,45.135 45.2,45.4 45.5,45.7 47.444,45.7 47.685,45.941 47.685,46.27 47.9,46.485 49.859,46.485 50.244,46.1 50.7,46.1 51.085,46.485 51.985,46.485 52.415,46.915 52.815,46.915 53.1,47.2 53.1,47.8 53.55,48.25 53.55,48.85 53.2,49.2 53.2,50.3 52.9,50.6 52.9,51 53.715,51.815 53.715,53.815 54.1,54.2 54.1,54.9 53.7,55.3 53.7,55.9 53.3,56.3 53.3,57.444 53.7,57.844 53.7,58.3 53.5,58.5 53.5,59.056 53.885,59.441 53.885,60.8 53.985,60.9 53.985,61.644 53.715,61.914 53.715,63.015 54.1,63.4 54.1,63.844 54.5,64.244 54.5,65.7 54.915,66.115 54.915,68.371 55.955,69.411 55.955,69.691 56.1,69.836 56.1,71.9 55.7,72.3 55.7,73.5 v1(56.1,73.9)
DRAM_A12: R106.1 U1.AD12 U2.N7 U3.N7 U4.N7 U5.N7 | length 109.6
  L1 w0.114: U1.AD12@38.8,47.7 39.2,47.3 v1(40.8,47.3) ; v1(54.1,31.5) U2.N7@54.1,32.1 ; v1(54.1,43.5) U3.N7@54.1,44.1 ; v1(54.1,55.5) U4.N7@54.1,56.1 ; v1(54.1,67.5) U5.N7@54.1,68.1 ; v1(60,25.8) 60.265,25.535 R106.1@60.5,25.535
  L8 w0.12: v1(53.6,72.6) 54,72.6 54.215,72.385 54.215,71.185 54.566,70.834 54.566,70.066 54.1,69.6 v1(54.1,67.5) 54.1,67.1 54.5,66.7 54.5,64.304 55,63.804 55,63.5 54.5,63 54.5,61.744 54.315,61.559 54.315,61.2 54.65,60.865 54.65,60.25 54.2,59.8 54.2,59.1 54.535,58.765 54.535,58.035 54.1,57.6 v1(54.1,55.5) 54.1,55.1 54.5,54.7 54.5,52.304 55,51.804 55,51.5 54.5,51 54.5,49.744 54.315,49.559 54.315,49.2 54.65,48.865 54.65,48.25 54.2,47.8 54.2,47.1 54.535,46.765 54.535,46.035 54.1,45.6 v1(54.1,43.5) 54.1,43.1 54.5,42.7 54.5,40.304 55,39.804 55,39.5 54.5,39 54.5,37.744 54.315,37.559 54.315,37.2 54.65,36.865 54.65,36.25 54.2,35.8 54.2,35.1 54.535,34.765 54.535,34.035 54.1,33.6 v1(54.1,31.5) 54.1,30.9 54.515,30.485 54.515,29.285 54.635,29.165 54.635,28.225 54.9,27.96 54.9,27.4 55.1,27.2 55.9,27.2 56.215,26.885 57.455,26.885 57.84,26.5 58.2,26.5 58.44,26.26 58.44,25.96 58.7,25.7 59.9,25.7 v1(60,25.8)
  L10 w0.114: v1(40.8,47.3) 40.6,47.3 40.4,47.5 40.4,47.9 40.6,48.1 41.9,48.1 42.3,47.7 42.9,47.7 43.385,47.215 45.659,47.215 45.9,47.456 45.9,47.744 46.156,48 46.8,48 47.1,48.3 49.6,48.3 49.87,48.03 50.33,48.03 50.8,48.5 50.8,48.9 50.5,49.2 50.5,49.5 50.3,49.7 50,49.7 49.8,49.9 49.8,50.3 50,50.5 50.7,50.5 50.9,50.7 50.9,51.1 50.7,51.3 49.5,51.3 49.3,51.5 49.3,51.9 49.5,52.1 50.3,52.1 50.515,52.315 50.515,53.659 50.741,53.885 51.385,53.885 51.6,54.1 51.6,54.904 51.304,55.2 51,55.2 50.8,55.4 50.8,55.8 51.1,56.1 51.5,56.1 51.7,56.3 51.7,56.7 51.5,56.9 51.1,56.9 50.9,57.1 50.9,57.5 51.1,57.7 51.5,57.7 51.7,57.9 51.7,58.244 51.3,58.644 51.3,58.96 51.68,59.34 51.68,60.876 51.315,61.241 51.315,61.615 51.6,61.9 51.6,62.256 51.315,62.541 51.315,62.944 51.715,63.344 51.715,65.659 52.5,66.444 52.5,66.9 52.1,67.3 52.1,67.7 52.534,68.134 52.534,68.78 52.822,69.068 52.822,69.478 53.4,70.056 53.4,70.244 53.9,70.744 53.9,71.9 54.4,72.4 54.4,73.2 54.2,73.4 53.8,73.4 53.6,73.2 v1(53.6,72.6)
DRAM_A13: R107.1 U1.AC17 U2.T3 U3.T3 U4.T3 U5.T3 | length 109.5
  L1 w0.114: U1.AC17@38,51.7 v1(38.4,52.1) ; U2.T3@56.5,28.9 v1(56.9,28.5) ; U3.T3@56.5,40.9 v1(56.9,40.5) ; U4.T3@56.5,52.9 v1(56.9,52.5) ; U5.T3@56.5,64.9 v1(56.9,64.5) ; R107.1@58.9,32.435 59.735,32.435 v1(59.9,32.6)
  L3 w0.12: v1(56.1,74.7) 56.1,74.444 56.515,74.029 56.515,73.685 57.6,72.6 57.6,72.244 57.3,71.944 57.3,71.4 56.9,71 56.9,70.644 57.4,70.144 57.4,69.246 56.815,68.661 56.815,68.341 57.5,67.656 57.5,67.4 57.1,67 57.1,66.6 57.3,66.4 57.3,65.1 56.9,64.7 v1(56.9,64.5) 56.9,64.244 57.3,63.844 57.3,63.2 57.7,62.8 57.7,59 57.3,58.6 57.3,57.156 56.815,56.671 56.815,56.341 57.31,55.846 57.31,54.4 57.6,54.11 57.6,53.6 57.3,53.3 57.3,53 56.9,52.6 v1(56.9,52.5) 56.9,52.244 57.3,51.844 57.3,51.2 57.7,50.8 57.7,47 57.3,46.6 57.3,45.156 56.815,44.671 56.815,44.341 57.31,43.846 57.31,42.4 57.6,42.11 57.6,41.6 57.3,41.3 57.3,41 56.9,40.6 v1(56.9,40.5) 56.9,40.244 57.3,39.844 57.3,39.2 57.7,38.8 57.7,35 57.3,34.6 57.3,33.156 56.815,32.671 56.815,32.321 57.31,31.826 57.31,30.4 57.6,30.11 57.6,29.6 57.3,29.3 57.3,29.1 56.9,28.7 v1(56.9,28.5) 56.971,28.5 57.106,28.365 57.175,28.365 57.34,28.2 58.2,28.2 58.485,28.485 58.485,28.755 58.8,29.07 58.8,29.4 58.315,29.885 58.315,30.259 58.541,30.485 58.915,30.485 59.6,29.8 60.044,29.8 60.285,30.041 60.285,31.215 60.1,31.4 59.7,31.4 59.35,31.75 59.35,32.35 59.6,32.6 v1(59.9,32.6)
  L10 w0.114: v1(38.4,52.1) 38.555,52.1 38.855,52.4 39.2,52.4 40,53.2 40,53.9 40.8,54.7 40.8,55.7 41.6,56.5 41.6,57.6 41.82,57.82 41.82,60.78 41.6,61 41.6,62.1 42,62.5 42,62.8 41.7,63.1 41.1,63.1 40.9,63.3 40.9,63.7 41.1,63.9 41.5,63.9 41.7,64.1 41.7,64.5 41.5,64.7 40.8,64.7 40.6,64.9 40.6,65.3 40.8,65.5 41.1,65.5 42.2,66.6 42.2,67.4 43.1,68.3 43.1,68.99 43.3,69.19 43.3,72 43.5,72.2 43.9,72.2 44.1,72 44.1,71.4 44.3,71.2 44.8,71.2 45,71.4 45,71.9 45.2,72.1 45.6,72.1 45.8,71.9 45.8,71.4 46,71.2 46.4,71.2 46.6,71.4 46.6,72.6 46.9,72.9 47.7,72.9 48.1,72.5 48.755,72.5 49.5,73.245 49.5,73.6 49.8,73.9 50.5,73.9 51.215,74.615 51.981,74.615 52.196,74.4 52.656,74.4 53.141,74.885 55.915,74.885 v1(56.1,74.7)
DRAM_A14: R108.1 U1.AA12 U2.T7 U3.T7 U4.T7 U5.T7 | length 110.6
  L1 w0.114: U1.AA12@36.4,47.7 v1(36.8,47.3) ; U2.T7@56.5,32.1 56.9,32.5 v1(57.2,32.5) ; U3.T7@56.5,44.1 56.9,44.5 v1(57.2,44.5) ; U4.T7@56.5,56.1 56.9,56.5 v1(57.2,56.5) ; U5.T7@56.5,68.1 56.9,68.5 v1(57.2,68.5) ; R108.1@60.165,34.5 60.5,34.165 60.5,33.7 v1(60.9,33.3)
  L3 w0.12: v1(57.5,73.9) 57.5,73.096 58.1,72.496 58.1,70.7 57.75,70.35 57.75,69.2 57.2,68.65 v1(57.2,68.5) 58.1,67.6 58.1,67.2 57.825,66.925 57.825,66.575 58.1,66.3 58.1,65.6 57.7,65.2 57.7,63.3 58.1,62.9 58.1,57.4 v1(57.2,56.5) 58.1,55.6 58.1,55.2 57.825,54.925 57.825,54.575 58.1,54.3 58.1,53.6 57.7,53.2 57.7,51.3 58.1,50.9 58.1,45.4 v1(57.2,44.5) 58.1,43.6 58.1,43.2 57.825,42.925 57.825,42.575 58.1,42.3 58.1,41.6 57.7,41.2 57.7,39.3 58.1,38.9 58.1,33.4 v1(57.2,32.5) 57.2,32.332 57.615,31.917 57.615,30.915 57.815,30.715 58.215,30.715 58.415,30.915 58.415,32.015 59.1,32.7 59.1,34.125 59.325,34.35 59.675,34.35 59.9,34.125 59.9,33.2 60.4,32.7 60.7,32.7 60.9,32.9 v1(60.9,33.3)
  L10 w0.114: v1(36.8,47.3) 36.8,47.044 37.215,46.629 37.215,46.341 37.471,46.085 37.759,46.085 39.729,44.115 40.585,44.115 40.9,43.8 46.8,43.8 47.915,44.915 52.259,44.915 53.7,46.356 53.7,46.7 54.215,47.215 54.215,47.815 54.315,47.915 54.315,49.559 54.515,49.759 54.515,51.115 54.915,51.515 54.915,52.815 55.3,53.2 55.3,54.3 54.9,54.7 54.9,58.244 55.015,58.359 55.015,59.759 55.1,59.844 55.1,61.8 55.3,62 55.3,63.3 55.7,63.7 55.7,66.656 56.515,67.471 56.515,69.459 56.771,69.715 57.059,69.715 57.285,69.941 57.285,73.685 v1(57.5,73.9)
DRAM_A15: R111.1 U1.Y12 U2.M7 U3.M7 U4.M7 U5.M7 | length 109.6
  L1 w0.114: U1.Y12@35.6,47.7 36,47.3 v1(36,46.5) ; v1(53.3,31.5) U2.M7@53.3,32.1 ; v1(53.3,43.5) U3.M7@53.3,44.1 ; v1(53.3,55.5) U4.M7@53.3,56.1 ; v1(53.3,67.5) U5.M7@53.3,68.1 ; v1(57.6,25.8) 57.765,25.635 R111.1@58.1,25.635
  L8 w0.12: v1(52,72.6) 52.256,72.6 53,71.856 53,71.415 52.8,71.215 52.8,70.865 53.32,70.345 53.32,69.92 52.9,69.5 52.9,68.2 53.3,67.8 v1(53.3,67.5) 53.3,66.4 53.7,66 53.7,63.744 52.9,62.944 52.9,62 53.215,61.685 53.215,61.185 53.5,60.9 53.5,60.2 53.115,59.815 53.115,58.429 53.285,58.259 53.285,57.941 52.9,57.556 52.9,56.253 53.3,55.853 v1(53.3,55.5) 53.3,54.4 53.7,54 53.7,51.744 52.9,50.944 52.9,50 53.215,49.685 53.215,49.185 53.5,48.9 53.5,48.2 53.115,47.815 53.115,46.429 53.285,46.259 53.285,45.941 52.9,45.556 52.9,44.253 53.3,43.853 v1(53.3,43.5) 53.3,42.4 53.7,42 53.7,39.744 52.9,38.944 52.9,38 53.215,37.685 53.215,37.185 53.5,36.9 53.5,36.2 53.115,35.815 53.115,34.429 53.285,34.259 53.285,33.941 52.9,33.556 52.9,32.253 53.3,31.853 v1(53.3,31.5) 53.3,30.1 53.7,29.7 53.7,26.444 54.585,25.559 54.585,25.271 54.841,25.015 55.315,25.015 55.7,25.4 56.3,25.4 56.5,25.2 57.256,25.2 57.6,25.544 v1(57.6,25.8)
  L10 w0.114: v1(36,46.5) 36.415,46.915 36.415,47.459 36.671,47.715 36.959,47.715 37.185,47.941 37.185,48.285 37.415,48.515 37.819,48.515 38.115,48.811 38.689,48.811 38.958,48.542 39.342,48.542 39.611,48.811 42.289,48.811 42.7,48.4 45.5,48.4 45.9,48.8 46.644,48.8 46.859,49.015 48.995,49.015 49.256,49.276 49.256,49.544 49,49.8 47.8,49.8 47.6,50 47.6,50.3 47.8,50.5 48.27,50.5 48.485,50.715 48.485,51.059 48.229,51.315 47.94,51.315 47.715,51.541 47.715,51.859 47.97,52.115 48.259,52.115 48.444,52.3 48.444,52.644 48.685,52.885 49.029,52.885 49.9,53.756 49.9,54.3 50.15,54.55 50.15,54.894 49.6,55.444 49.6,55.8 50.085,56.285 50.085,56.659 49.844,56.9 49.5,56.9 49.3,57.1 49.3,57.5 49.5,57.7 50,57.7 50.2,57.9 50.2,58.284 49.992,58.492 49.808,58.492 49.6,58.7 49.6,59 50.3,59.7 50.556,59.7 50.8,59.944 50.8,60.4 49.7,61.5 49.7,61.9 49.9,62.1 50.3,62.1 50.5,62.3 50.5,65.644 51.5,66.644 51.5,67 51.285,67.215 51.041,67.215 50.815,67.441 50.815,67.759 51.041,67.985 51.329,67.985 51.974,68.63 51.974,69.174 52.1,69.3 52.1,70.3 52.5,70.7 52.5,71 52.1,71.4 52.1,71.7 52.4,72 52.4,72.2 v1(52,72.6)
DRAM_CAS_B: R39.1 U1.AE16 U2.K3 U3.K3 U4.K3 U5.K3 | length 109.5
  L1 w0.114: U1.AE16@39.6,50.9 39.8,51.1 v1(40.4,51.1) ; U2.K3@51.7,28.9 v1(52.1,28.5) ; U3.K3@51.7,40.9 v1(52.1,40.5) ; U4.K3@51.7,52.9 v1(52.1,52.5) ; U5.K3@51.7,64.9 v1(52.1,64.5) ; R39.1@57.2,23.035 57.2,22.4 v1(57.4,22.2)
  L3 w0.12: v1(50.2,73.4) 49.8,73 48.7,73 48.5,72.8 48.5,72.4 48.7,72.2 50.3,72.2 50.5,72 50.5,71.8 49.8,71.1 49.8,70.7 50,70.5 50.4,70.5 51.1,71.2 51.5,71.2 51.7,71 51.7,65.1 52.1,64.7 v1(52.1,64.5) 52.1,64.314 51.7,63.914 51.7,63.5 51.225,63.025 51.225,62.631 51.6,62.256 51.6,61.9 51.3,61.6 51.3,61.2 50.9,60.8 50.9,60.3 51.5,59.7 51.5,59.14 51.7,58.94 51.7,53.156 52.1,52.756 v1(52.1,52.5) 52.1,52.314 51.7,51.914 51.7,51.5 51.225,51.025 51.225,50.631 51.6,50.256 51.6,49.9 51.3,49.6 51.3,49.2 50.9,48.8 50.9,48.3 51.5,47.7 51.5,47.14 51.7,46.94 51.7,41.156 52.1,40.756 v1(52.1,40.5) 52.1,40.314 51.7,39.914 51.7,39.5 51.225,39.025 51.225,38.631 51.6,38.256 51.6,37.9 51.3,37.6 51.3,37.2 50.9,36.8 50.9,36.3 51.5,35.7 51.5,35.14 51.7,34.94 51.7,29.156 52.1,28.756 v1(52.1,28.5) 52.1,28.244 51.685,27.829 51.685,26.715 52.2,26.2 52.2,25.256 54.256,23.2 56.5,23.2 57.4,22.3 v1(57.4,22.2)
  L10 w0.114: v1(40.4,51.1) 40.4,51.4 41.015,52.015 42.679,52.015 43.6,52.936 43.6,55 43.915,55.315 44.985,55.315 45.185,55.515 45.185,55.915 44.985,56.115 44,56.115 43.8,56.315 43.8,56.815 44.1,57.115 44.1,57.9 44.685,58.485 45.87,58.485 46.1,58.715 46.1,59.015 45.9,59.215 45.141,59.215 44.915,59.441 44.915,59.759 45.156,60 46.4,60 46.7,60.3 46.7,60.7 46.385,61.015 45.331,61.015 45.106,61.24 45.106,61.6 45.306,61.8 46.1,61.8 46.9,62.6 46.9,63.044 46.644,63.3 45.9,63.3 45.7,63.5 45.7,63.9 45.9,64.1 46.7,64.1 46.9,64.3 46.9,64.7 46.7,64.9 45.555,64.9 45.315,65.141 45.315,65.429 44.932,65.813 44.932,67.488 45.559,68.115 46.709,68.115 46.9,68.306 46.9,68.644 47.156,68.9 47.444,68.9 47.685,69.141 47.685,69.885 48,70.2 48.4,70.2 49.015,70.815 49.015,71.545 49.8,72.33 49.8,73 v1(50.2,73.4)
DRAM_CLK0_N: C327.2 R112.2 U1.AE15 U2.K7 U3.K7 U4.K7 U5.K7 | length 110.5
  L1 w0.1: U1.AE15@39.6,50.1 39.853,50.1 40.098,50.345 40.67,50.345 40.78,50.235 41.22,50.235 41.39,50.405 41.846,50.405 43.3,51.859 43.3,52.95 43.55,53.2 44.209,53.2 44.66,53.651 44.66,54.549 44.049,55.16 43.34,55.16 42.7,55.8 42.7,56.1 43.1,56.5 43.1,56.8 42.7,57.2 42.7,57.456 43.4,58.156 43.4,58.867 42.96,59.307 42.96,59.949 41.5,61.409 41.5,65.3 42.04,65.84 43.795,65.84 44.305,66.351 44.305,67.204 43.742,67.767 41.942,67.767 40.17,69.54 40.17,69.93 40.624,70.385 41.115,70.385 42.16,69.34 43.049,69.34 43.76,70.051 43.76,70.949 42.3,72.409 42.3,73.6 42.7,74 44.3,74 45.46,72.84 47.749,72.84 48.16,73.251 48.16,74.46 v1(48.3,74.6) ; v1(50.05,22.55) 50.1,22.6 R112.2@50.1,23.035 ; v1(51.2,31.6) U2.K7@51.7,32.1 ; v1(51.2,43.6) U3.K7@51.7,44.1 ; v1(51.2,55.6) U4.K7@51.7,56.1 ; v1(51.2,67.6) U5.K7@51.7,68.1
  L8 w0.11: v1(48.3,74.6) 48.16,74.46 48.16,73.19 49.23,72.12 49.833,72.12 50.5,71.453 50.5,68.753 50.96,68.293 50.96,67.84 v1(51.2,67.6) 50.96,67.36 50.96,66.46 50.52,66.02 50.52,62.62 49.85,61.95 49.85,61.303 50.32,60.833 50.32,59.82 50.1,59.6 50.1,58.853 50.52,58.433 50.52,56.673 50.96,56.233 50.96,55.84 v1(51.2,55.6) 50.96,55.36 50.96,54.46 50.52,54.02 50.52,50.62 49.85,49.95 49.85,49.303 50.32,48.833 50.32,47.82 50.1,47.6 50.1,46.853 50.52,46.433 50.52,44.673 50.96,44.233 50.96,43.84 v1(51.2,43.6) 50.96,43.36 50.96,42.46 50.52,42.02 50.52,38.62 49.85,37.95 49.85,37.303 50.32,36.833 50.32,35.82 50.1,35.6 50.1,33.953 50.52,33.533 50.52,32.673 50.96,32.233 50.96,31.84 v1(51.2,31.6) 50.96,31.36 50.96,30.96 50,30 50,29.6 50.65,28.95 50.65,26.797 50,26.147 50,25.3 50.62,24.68 50.62,24.02 49.91,23.31 49.91,22.69 v1(50.05,22.55)
DRAM_CLK0_P: C327.1 R253.2 U1.AD15 U2.J7 U3.J7 U4.J7 U5.J7 | length 110.5
  L1 w0.1: U1.AD15@38.8,50.1 39.07,50.1 39.45,50.48 39.78,50.48 39.965,50.665 40.64,50.665 40.74,50.765 C327.1@41,50.765 41.235,50.765 41.275,50.725 41.714,50.725 42.98,51.991 42.98,53.083 43.417,53.52 44.077,53.52 44.34,53.783 44.34,54.417 43.917,54.84 43.207,54.84 42.38,55.667 42.38,57.588 43.08,58.288 43.08,58.735 42.64,59.175 42.64,59.817 41.18,61.277 41.18,65.433 41.907,66.16 43.662,66.16 43.985,66.483 43.985,67.071 43.609,67.447 41.809,67.447 39.85,69.407 39.85,70.063 40.492,70.705 41.248,70.705 42.293,69.66 42.917,69.66 43.44,70.183 43.44,70.817 41.98,72.277 41.98,73.733 42.567,74.32 44.433,74.32 45.593,73.16 47.617,73.16 47.84,73.383 47.84,74.46 v1(47.7,74.6) ; R253.2@49.4,23.035 49.4,22.6 v1(49.45,22.55) ; v1(50.4,31.6) U2.J7@50.9,32.1 ; v1(50.4,43.6) U3.J7@50.9,44.1 ; v1(50.4,55.6) U4.J7@50.9,56.1 ; v1(50.4,67.6) U5.J7@50.9,68.1
  L8 w0.11: v1(47.7,74.6) 47.84,74.46 47.84,73.057 49.097,71.8 49.7,71.8 50.18,71.32 50.18,68.62 50.64,68.16 50.64,67.84 v1(50.4,67.6) 50.64,67.36 50.64,66.593 50.2,66.153 50.2,62.753 49.53,62.083 49.53,61.17 50,60.7 50,59.953 49.78,59.733 49.78,58.72 50.2,58.3 50.2,56.54 50.64,56.1 50.64,55.84 v1(50.4,55.6) 50.64,55.36 50.64,54.593 50.2,54.153 50.2,50.753 49.53,50.083 49.53,49.17 50,48.7 50,47.953 49.78,47.733 49.78,46.72 50.2,46.3 50.2,44.54 50.64,44.1 50.64,43.84 v1(50.4,43.6) 50.64,43.36 50.64,42.593 50.2,42.153 50.2,38.753 49.53,38.083 49.53,37.17 50,36.7 50,35.953 49.78,35.733 49.78,33.82 50.2,33.4 50.2,32.54 50.64,32.1 50.64,31.84 v1(50.4,31.6) 50.64,31.36 50.64,31.093 49.68,30.133 49.68,29.467 50.33,28.817 50.33,26.93 49.68,26.28 49.68,25.167 50.3,24.547 50.3,24.153 49.59,23.443 49.59,22.69 v1(49.45,22.55)
DRAM_CLK0_T_CAP: C322.1 R112.1 R253.1 | length 1.6
  L1 w0.3: R253.1@49.4,23.565 R112.1@50.1,23.565 50.465,23.93 C322.1@50.465,24.3
DRAM_CLK1_N: C328.2 R113.2 U1.AE14 | length 3.2
  L1 w0.1: U1.AE14@39.6,49.3 39.847,49.3 40.167,49.62 41.48,49.62 41.565,49.535 C328.2@41.565,49.3 41.565,49.265 41.355,49.055 41.355,48.865 R113.2@41.555,48.665 ; R113.2@41.565,48.655 R113.2@41.555,48.665 ; R113.2@41.6,48.665 R113.2@41.555,48.665
DRAM_CLK1_P: C328.1 R256.2 U1.AD14 | length 3.2
  L1 w0.1: U1.AD14@38.8,49.3 39.1,49.3 39.5,48.9 39.9,48.9 40.3,49.3 C328.1@41.035,49.3 41.035,48.7 R256.2@41,48.665
DRAM_CLK1_T_CAP: C323.1 R113.1 R256.1 | length 2
  L1 w0.3: R256.1@41,48.135 41.561,48.135 R113.1@41.6,48.096 ; R113.1@41.6,48.135 R113.1@41.6,48.096 ; C323.1@42.1,46.965 42.1,47.472 41.6,47.972 R113.1@41.6,48.096
DRAM_CS0_B: R66.1 U1.Y16 U2.L2 U3.L2 U4.L2 U5.L2 | length 109.5
  L1 w0.114: U1.Y16@35.6,50.9 36,51.3 v1(36,52.1) ; U2.L2@52.5,28.1 v1(52.9,27.7) ; U3.L2@52.5,40.1 v1(52.9,39.7) ; U4.L2@52.5,52.1 v1(52.9,51.7) ; U5.L2@52.5,64.1 v1(52.9,63.7) ; v1(59.2,25) 59.365,25.165 R66.1@59.365,25.5
  L8 w0.12: v1(50.6,75) 51,74.6 51,73.555 51.6,72.955 51.6,72.456 52.2,71.856 52.2,71.147 52.5,70.847 52.5,68.153 52.9,67.753 52.9,65.3 53.3,64.9 53.3,64.356 52.9,63.956 v1(52.9,63.7) 52.9,63.418 52.58,63.098 52.58,62.08 52.4,61.9 52.4,61.2 52.7,60.9 52.7,60.4 52.3,60 52.3,59.4 52.725,58.975 52.725,58.525 52.44,58.24 52.44,56.16 52.9,55.7 52.9,53.1 53.3,52.7 53.3,52.1 v1(52.9,51.7) 52.9,51.418 52.58,51.098 52.58,50.08 52.4,49.9 52.4,49.2 52.7,48.9 52.7,48.4 52.3,48 52.3,47.4 52.725,46.975 52.725,46.525 52.44,46.24 52.44,44.16 52.9,43.7 52.9,41.1 53.3,40.7 53.3,40.1 v1(52.9,39.7) 52.9,39.418 52.58,39.098 52.58,38.08 52.4,37.9 52.4,37.2 52.7,36.9 52.7,36.4 52.3,36 52.3,35.4 52.725,34.975 52.725,34.525 52.44,34.24 52.44,32.16 52.9,31.7 52.9,29.1 53.3,28.7 53.3,28.1 v1(52.9,27.7) 52.9,26.5 53.8,25.6 53.8,25.256 54.3,24.756 54.3,23.7 54.5,23.5 54.9,23.5 55.1,23.7 55.1,24.2 55.5,24.6 58.8,24.6 v1(59.2,25)
  L10 w0.114: v1(36,52.1) 36,52.3 35.615,52.685 35.615,53.115 35.785,53.285 36.129,53.285 36.415,53.571 36.415,53.859 36.671,54.115 36.959,54.115 37.215,54.371 37.215,56.259 37.441,56.485 37.785,56.485 38,56.7 38,57.1 38.4,57.5 38.4,57.915 38,58.315 38,59.485 37.233,60.252 37.233,61.833 38.067,62.667 38.067,64.167 38.3,64.4 38.3,65.885 38.9,66.485 38.9,67 38.7,67.2 38.1,67.2 37.9,67.4 37.9,67.8 38.1,68 38.535,68 38.8,68.265 38.8,68.6 38.6,68.8 37.705,68.8 37.505,69 37.505,69.4 37.705,69.6 38.7,69.6 38.9,69.8 38.9,70.2 38.7,70.4 38.4,70.4 38.2,70.6 38.2,71 38.4,71.2 39.2,71.2 42.3,74.3 42.3,75.6 42.8,76.1 43.465,76.1 43.765,75.8 44.2,75.8 44.5,76.1 45.1,76.1 45.4,75.8 45.8,75.8 46.1,76.1 46.7,76.1 47.415,75.385 50.215,75.385 v1(50.6,75)
DRAM_D0: U1.AD2 U2.E3 | length 19.1
  L1 w0.114: U1.AD2@38.8,39.7 39.2,39.3 v1(39.2,38.5) ; v1(47.3,28.5) U2.E3@47.7,28.9
  L8 w0.12: v1(39.2,38.5) 39.6,38.9 40.2,38.9 40.4,38.7 40.4,38.1 40.2,37.9 39.85,37.9 39.6,37.65 39.6,37 41.2,35.4 41.2,34.404 42.6,33.004 42.6,30.5 42.9,30.2 43.2,30.2 43.4,30 43.4,29.7 43.7,29.4 44.2,29.4 44.7,28.9 45.96,28.9 46.36,28.5 v1(47.3,28.5)
DRAM_D1: U1.AE2 U2.H3 | length 19
  L1 w0.114: U1.AE2@39.6,39.7 v1(40,39.3) ; v1(47.3,29.3) 47.7,29.7 49.3,29.7 U2.H3@50.1,28.9
  L8 w0.12: v1(40,39.3) 40.3,39.3 40.9,38.7 40.9,37.7 40.7,37.5 40.7,36.4 41.6,35.5 41.6,34.456 43,33.056 43,31.05 44.365,29.685 45.571,29.685 46.341,28.915 46.915,28.915 v1(47.3,29.3)
DRAM_D2: U1.AC4 U2.H7 | length 19
  L1 w0.114: U1.AC4@38,41.3 v1(38.4,40.9) ; v1(49.6,31.6) U2.H7@50.1,32.1
  L8 w0.12: v1(38.4,40.9) 38.555,40.9 38.955,40.5 40.4,40.5 41.1,39.8 41.8,39.8 43.015,38.585 43.471,38.585 43.821,38.235 44.865,38.235 45.315,37.785 45.315,37.241 45.541,37.015 46.735,37.015 47,36.75 47,36.3 46.72,36.02 46.72,35.32 46.915,35.125 46.915,33.141 47.141,32.915 47.53,32.915 47.945,32.5 48.355,32.5 48.755,32.1 49.1,32.1 v1(49.6,31.6)
DRAM_D3: U1.AA5 U2.F8 | length 19
  L1 w0.114: U1.AA5@36.4,42.1 v1(36.8,41.7) ; v1(48.1,33.3) U2.F8@48.5,32.9
  L8 w0.12: v1(36.8,41.7) 37.2,41.3 40.156,41.3 40.541,41.685 41.371,41.685 43.056,40 43.456,40 43.756,39.7 44.355,39.7 44.77,39.285 46.915,39.285 47.815,38.385 47.815,35.985 47.915,35.885 47.915,35 48.1,34.815 v1(48.1,33.3)
DRAM_D4: U1.AC1 U2.F2 | length 19
  L1 w0.114: U1.AC1@38,38.9 38,38.1 v1(38.4,37.7) ; v1(48.1,27.7) U2.F2@48.5,28.1
  L8 w0.12: v1(38.4,37.7) 38.745,37.355 38.745,36.7 40.4,35.045 40.4,34.1 41.115,33.385 41.115,30.285 43.315,28.085 45.059,28.085 45.285,27.859 45.285,27.571 45.541,27.315 47.715,27.315 v1(48.1,27.7)
DRAM_D5: U1.AD1 U2.G2 | length 19
  L1 w0.114: U1.AD1@38.8,38.9 38.8,38.1 v1(39.2,37.7) ; v1(48.9,27.7) U2.G2@49.3,28.1
  L8 w0.12: v1(39.2,37.7) 39.2,36.8 40.8,35.2 40.8,34.3 42.1,33 42.1,32.2 41.9,32 41.9,31.5 42.1,31.3 42.1,29.856 43.306,28.65 43.65,28.65 43.9,28.9 44.244,28.9 44.644,28.5 45.1,28.5 45.5,28.1 48.244,28.1 48.644,27.7 v1(48.9,27.7)
DRAM_D6: U1.AB4 U2.F7 | length 19
  L1 w0.114: U1.AB4@37.2,41.3 v1(37.6,40.9) ; U2.F7@48.5,32.1 v1(48.9,31.7)
  L8 w0.12: v1(37.6,40.9) 37.985,40.515 38.529,40.515 38.944,40.1 40.404,40.1 40.984,39.52 41.336,39.52 43.156,37.7 43.556,37.7 43.756,37.9 44.644,37.9 45.035,37.509 45.035,37.061 45.396,36.7 45.9,36.7 46.2,36.4 46.2,36.1 45.9,35.8 45.9,35.1 46.1,34.9 46.1,33.156 46.371,32.885 46.659,32.885 46.885,32.659 46.885,32.371 47.141,32.115 48.345,32.115 48.76,31.7 v1(48.9,31.7)
DRAM_D7: U1.AE4 U2.H8 | length 19
  L1 w0.114: U1.AE4@39.6,41.3 v1(40,40.9) ; v1(49.7,32.5) U2.H8@50.1,32.9
  L8 w0.12: v1(40,40.9) 40.6,40.9 40.8,40.7 41.2,40.7 41.4,40.9 41.744,40.9 42.185,40.459 42.185,40.015 43,39.2 44.056,39.2 44.741,38.515 45.385,38.515 45.6,38.3 45.6,38 45.8,37.8 46.2,37.8 46.4,38 46.4,38.3 46.6,38.5 47.1,38.5 47.3,38.3 47.3,37.9 47,37.6 47,37.256 47.5,36.756 47.5,36.3 47.1,35.9 47.1,35.336 47.7,34.736 47.7,33.156 47.941,32.915 49.285,32.915 v1(49.7,32.5)
DRAM_D8: U1.AD5 U2.D7 | length 20.4
  L1 w0.114: U1.AD5@38.8,42.1 v1(39.2,41.7) ; U2.D7@46.9,32.1 v1(47.3,32.5)
  L3 w0.12: v1(39.2,41.7) 39.4,41.7 39.756,41.344 40.2,41.344 40.656,41.8 41.075,41.8 41.308,41.567 41.308,41.092 41.5,40.9 42.1,40.9 42.485,40.515 42.929,40.515 43.8,39.644 43.8,39.404 44.215,38.989 44.215,37.185 44.68,36.72 45.2,36.72 45.4,36.52 45.4,36.22 45.18,36 44.4,36 44.2,35.8 44.2,35.4 44.405,35.195 45.505,35.195 45.685,35.015 45.685,34.615 45.315,34.245 45.315,33.8 45.7,33.415 45.7,33.044 45.315,32.659 45.315,32.341 45.541,32.115 46.915,32.115 v1(47.3,32.5)
DRAM_D9: U1.AE5 U2.C3 | length 20.4
  L1 w0.114: U1.AE5@39.6,42.1 40.4,41.3 v1(40.7,41.3) ; U2.C3@46.1,28.9 v1(46.5,29.3)
  L3 w0.12: v1(40.7,41.3) 40.45,41.05 40.45,40.046 41.015,39.481 41.015,38.4 41.4,38.015 41.4,36.956 41.556,36.8 41.556,35.7 42.4,34.856 42.4,33.856 42.6,33.656 42.6,32.2 42.85,31.95 42.85,31.588 42.6,31.338 42.6,31.055 44.77,28.885 45.859,28.885 46.1,28.644 46.1,28.3 46.3,28.1 46.7,28.1 46.9,28.3 46.9,28.9 v1(46.5,29.3)
DRAM_D10: U1.AA6 U2.B8 | length 20.4
  L1 w0.114: v1(36,43.3) U1.AA6@36.4,42.9 ; U2.B8@45.3,32.9 45.7,33.3 v1(46.5,33.3)
  L3 w0.12: v1(36,43.3) 36.4,42.9 38.66,42.9 39.06,42.5 41.6,42.5 42.52,41.58 43.02,41.58 43.6,41 44.05,41 44.48,40.57 44.48,39.525 44.69,39.315 45.085,39.315 45.315,39.085 45.315,38.085 45.5,37.9 45.8,37.9 46.115,37.585 46.115,37.185 46.7,36.6 46.7,36 46.9,35.8 46.9,33.7 v1(46.5,33.3)
DRAM_D11: U1.AE7 U2.C8 | length 20.4
  L1 w0.114: U1.AE7@39.6,43.7 40,43.7 v1(40.4,43.3) ; U2.C8@46.1,32.9 v1(46.5,32.5)
  L3 w0.12: v1(40.4,43.3) 40.9,42.8 41.892,42.8 42.792,41.9 43.19,41.9 43.79,41.3 44.2,41.3 44.615,40.885 45.059,40.885 45.3,40.644 45.3,39.496 45.7,39.096 45.7,38.475 46.375,37.8 47.6,37.8 47.8,37.6 47.8,37.2 47.6,37 47.4,37 47.2,36.8 47.2,36.444 47.9,35.744 47.9,35.4 47.7,35.2 47.5,35.2 47.3,35 47.3,34.7 47.5,34.5 48.1,34.5 48.3,34.3 48.3,33.9 48.1,33.7 47.9,33.7 47.7,33.5 47.7,33.156 47.459,32.915 46.915,32.915 v1(46.5,32.5)
DRAM_D12: U1.AB5 U2.C2 | length 20.4
  L1 w0.114: U1.AB5@37.2,42.1 v1(37.6,41.7) ; v1(45.7,27.7) U2.C2@46.1,28.1
  L3 w0.12: v1(37.6,41.7) 37.985,41.315 37.985,40.771 38.271,40.485 38.559,40.485 39.065,39.979 39.065,39.179 39.585,38.659 39.585,37.541 39.4,37.356 39.4,36.668 41.085,34.983 41.085,32.941 40.758,32.613 40.758,30.342 42.35,28.75 42.79,28.75 43.26,28.28 43.776,28.28 43.956,28.1 45.3,28.1 v1(45.7,27.7)
DRAM_D13: U1.AC5 U2.A3 | length 20.4
  L1 w0.114: U1.AC5@38,42.1 v1(38.4,41.7) ; v1(44.1,28.5) U2.A3@44.5,28.9
  L3 w0.12: v1(38.4,41.7) 38.4,41.56 38.785,41.175 38.785,40.715 39.5,40 39.5,39.256 39.871,38.885 40.159,38.885 40.385,38.659 40.385,37.585 40.2,37.4 39.9,37.4 39.7,37.2 39.7,36.8 39.9,36.6 40.6,36.6 40.8,36.4 40.8,35.664 41.6,34.864 41.6,33.06 41.115,32.575 41.115,32.241 41.6,31.756 41.6,31.5 41.115,31.015 41.115,30.685 41.4,30.4 41.7,30.4 41.9,30.6 42.2,30.6 42.4,30.4 42.4,30.1 42.1,29.8 42.1,29.5 42.5,29.1 42.856,29.1 43.396,28.56 44.04,28.56 v1(44.1,28.5)
DRAM_D14: U1.AB6 U2.A2 | length 20.4
  L1 w0.114: v1(36.8,42.5) U1.AB6@37.2,42.9 ; v1(44.1,27.7) U2.A2@44.5,28.1
  L3 w0.12: v1(36.8,42.5) 37.2,42.1 37.2,40.756 37.471,40.485 37.815,40.485 38.015,40.285 38.015,39.941 38.271,39.685 38.559,39.685 38.785,39.459 38.785,36.815 40.7,34.9 40.7,33.715 40.285,33.3 40.285,32.815 40.4,32.7 40.4,30.1 42.1,28.4 42.744,28.4 43.159,27.985 43.459,27.985 43.744,27.7 v1(44.1,27.7)
DRAM_D15: U1.AC7 U2.A7 | length 20.4
  L1 w0.114: U1.AC7@38,43.7 38.4,43.3 v1(38.4,42.5) ; U2.A7@44.5,32.1 44.9,32.5 v1(45.7,32.5)
  L3 w0.12: v1(38.4,42.5) 38.664,42.5 38.964,42.2 39.5,42.2 39.7,42 40.3,42 40.5,42.2 41.4,42.2 41.7,41.9 41.7,41.55 41.965,41.285 42.859,41.285 43.544,40.6 44,40.6 44.2,40.4 44.2,39.4 44.515,39.085 44.515,38.285 45.035,37.765 45.035,37.265 45.3,37 45.8,37 46.3,36.5 46.3,36.2 45.9,35.8 45.9,35.4 46.1,35.2 46.4,35.2 46.6,35 46.6,34.7 46.4,34.5 46,34.5 45.7,34.2 45.7,33.9 46.1,33.5 46.1,32.9 v1(45.7,32.5)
